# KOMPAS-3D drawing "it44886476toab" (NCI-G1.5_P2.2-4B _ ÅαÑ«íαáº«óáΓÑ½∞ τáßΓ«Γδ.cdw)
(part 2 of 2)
  Кривая без истории:10763
  Кривая без истории:10764
  Кривая без истории:10765
  Кривая без истории:10766
  Кривая без истории:10767
  Кривая без истории:10768
  Кривая без истории:10769
  Кривая без истории:10770
  Кривая без истории:10771
  Кривая без истории:10772
  Кривая без истории:10773
  Кривая без истории:10774
  Кривая без истории:10775
  Кривая без истории:10776
  Кривая без истории:10777
  Кривая без истории:10778
  Кривая без истории:10779
  Кривая без истории:10780
  Кривая без истории:10781
  Кривая без истории:10782
  Кривая без истории:10783
  Кривая без истории:10784
  Кривая без истории:10785
  Кривая без истории:10786
  Кривая без истории:10787
  Кривая без истории:10788
  Кривая без истории:10789
  Кривая без истории:10790
  Кривая без истории:10791
  Кривая без истории:10792
  Кривая без истории:10793
  Кривая без истории:10794
  Кривая без истории:10795
  Кривая без истории:10796
  Кривая без истории:10797
  Кривая без истории:10798
  Кривая без истории:10799
  Кривая без истории:10800
  Кривая без истории:10801
  Кривая без истории:10802
  Кривая без истории:10803
  Кривая без истории:10804
  Кривая без истории:10805
  Кривая без истории:10806
  Кривая без истории:10807
  Кривая без истории:10808
  Кривая без истории:10809
  Кривая без истории:10810
  Кривая без истории:10811
  Кривая без истории:10812
  Кривая без истории:10813
  Кривая без истории:10814
  Кривая без истории:10815
  Кривая без истории:10816
  Кривая без истории:10817
  Кривая без истории:10818
  Кривая без истории:10819
  Кривая без истории:10820
  Кривая без истории:10821
  Кривая без истории:10822
  Кривая без истории:10823
  Кривая без истории:10824
  Кривая без истории:10825
  Кривая без истории:10826
  Кривая без истории:10827
  Кривая без истории:10828
  Кривая без истории:10829
  Кривая без истории:10830
  Кривая без истории:10831
  Кривая без истории:10832
  Кривая без истории:10833
  Кривая без истории:10834
  Кривая без истории:10835
  Кривая без истории:10836
  Кривая без истории:10837
  Кривая без истории:10838
  Кривая без истории:10839
  Кривая без истории:10840
  Кривая без истории:10841
  Кривая без истории:10842
  Кривая без истории:10843
  Кривая без истории:10844
  Кривая без истории:10845
  Кривая без истории:10846
  Кривая без истории:10847
  Кривая без истории:10848
  Кривая без истории:10849
  Кривая без истории:10850
  Кривая без истории:10851
  Кривая без истории:10852
  Кривая без истории:10853
  Кривая без истории:10854
  Кривая без истории:10855
  Кривая без истории:10856
  Кривая без истории:10857
  Кривая без истории:10858
  Кривая без истории:10859
  Кривая без истории:10860
  Кривая без истории:10861
  Кривая без истории:10862
  Кривая без истории:10863
  Кривая без истории:10864
  Кривая без истории:10865
  Кривая без истории:10866
  Кривая без истории:10867
  Кривая без истории:10868
  Кривая без истории:10869
  Кривая без истории:10870
  Кривая без истории:10871
  Кривая без истории:10872
  Кривая без истории:10873
  Кривая без истории:10874
  Кривая без истории:10875
  Кривая без истории:10876
  Кривая без истории:10877
  Кривая без истории:10878
  Кривая без истории:10879
  Кривая без истории:10880
  Кривая без истории:10881
  Кривая без истории:10882
  Кривая без истории:10883
  Кривая без истории:10884
  Кривая без истории:10885
  Кривая без истории:10886
  Кривая без истории:10887
  Кривая без истории:10888
  Кривая без истории:10889
  Кривая без истории:10890
  Кривая без истории:10891
  Кривая без истории:10892
  Кривая без истории:10893
  Кривая без истории:10894
  Кривая без истории:10895
  Кривая без истории:10896
  Кривая без истории:10897
  Кривая без истории:10898
  Кривая без истории:10899
  Кривая без истории:10900
  Кривая без истории:10901
  Кривая без истории:10902
  Кривая без истории:10903
  Кривая без истории:10904
  Кривая без истории:10905
  Кривая без истории:10906
  Кривая без истории:10907
  Кривая без истории:10908
  Кривая без истории:10909
  Кривая без истории:10910
  Кривая без истории:10911
  Кривая без истории:10912
  Кривая без истории:10913
  Кривая без истории:10914
  Кривая без истории:10915
  Кривая без истории:10916
  Кривая без истории:10917
  Кривая без истории:10918
  Кривая без истории:10919
  Кривая без истории:10920
  Кривая без истории:10921
  Кривая без истории:10922
  Кривая без истории:10923
  Кривая без истории:10924
  Кривая без истории:10925
  Кривая без истории:10926
  Кривая без истории:10927
  Кривая без истории:10928
  Кривая без истории:10929
  Кривая без истории:10930
  Кривая без истории:10931
  Кривая без истории:10932
  Кривая без истории:10933
  Кривая без истории:10934
  Кривая без истории:10935
  Кривая без истории:10936
  Кривая без истории:10937
  Кривая без истории:10938
  Кривая без истории:10939
  Кривая без истории:10940
  Кривая без истории:10941
  Кривая без истории:10942
  Кривая без истории:10943
  Кривая без истории:10944
  Кривая без истории:10945
  Кривая без истории:10946
  Кривая без истории:10947
  Кривая без истории:10948
  Кривая без истории:10949
  Кривая без истории:10950
  Кривая без истории:10951
  Кривая без истории:10952
  Кривая без истории:10953
  Кривая без истории:10954
  Кривая без истории:10955
  Кривая без истории:10956
  Кривая без истории:10957
  Кривая без истории:10958
  Кривая без истории:10959
  Кривая без истории:10960
  Кривая без истории:10961
  Кривая без истории:10962
  Кривая без истории:10963
  Кривая без истории:10964
  Кривая без истории:10965
  Кривая без истории:10966
  Кривая без истории:10967
  Кривая без истории:10968
  Кривая без истории:10969
  Кривая без истории:10970
  Кривая без истории:10971
  Кривая без истории:10972
  Кривая без истории:10973
  Кривая без истории:10974
  Кривая без истории:10975
  Кривая без истории:10976
  Кривая без истории:10977
  Кривая без истории:10978
  Кривая без истории:10979
  Кривая без истории:10980
  Кривая без истории:10981
  Кривая без истории:10982
  Кривая без истории:10983
  Кривая без истории:10984
  Кривая без истории:10985
  Кривая без истории:10986
  Кривая без истории:10987
  Кривая без истории:10988
  Кривая без истории:10989
  Кривая без истории:10990
  Кривая без истории:10991
  Кривая без истории:10992
  Кривая без истории:10993
  Кривая без истории:10994
  Кривая без истории:10995
  Кривая без истории:10996
  Кривая без истории:10997
  Кривая без истории:10998
  Кривая без истории:10999
  Кривая без истории:11000
  Кривая без истории:11001
  Кривая без истории:11002
  Кривая без истории:11003
  Кривая без истории:11004
  Кривая без истории:11005
  Кривая без истории:11006
  Кривая без истории:11007
  Кривая без истории:11008
  Кривая без истории:11009
  Кривая без истории:11010
  Кривая без истории:11011
  Кривая без истории:11012
  Кривая без истории:11013
  Кривая без истории:11014
  Кривая без истории:11015
  Кривая без истории:11016
  Кривая без истории:11017
  Кривая без истории:11018
  Кривая без истории:11019
  Кривая без истории:11020
  Кривая без истории:11021
  Кривая без истории:11022
  Кривая без истории:11023
  Кривая без истории:11024
  Кривая без истории:11025
  Кривая без истории:11026
  Кривая без истории:11027
  Кривая без истории:11028
  Кривая без истории:11029
  Кривая без истории:11030
  Кривая без истории:11031
  Кривая без истории:11032
  Кривая без истории:11033
  Кривая без истории:11034
  Кривая без истории:11035
  Кривая без истории:11036
  Кривая без истории:11037
  Кривая без истории:11038
  Кривая без истории:11039
  Кривая без истории:11040
  Кривая без истории:11041
  Кривая без истории:11042
  Кривая без истории:11043
  Кривая без истории:11044
  Кривая без истории:11045
  Кривая без истории:11046
  Кривая без истории:11047
  Кривая без истории:11048
  Кривая без истории:11049
  Кривая без истории:11050
  Кривая без истории:11051
  Кривая без истории:11052
  Кривая без истории:11053
  Кривая без истории:11054
  Кривая без истории:11055
  Кривая без истории:11056
  Кривая без истории:11057
  Кривая без истории:11058
  Кривая без истории:11059
  Кривая без истории:11060
  Кривая без истории:11061
  Кривая без истории:11062
  Кривая без истории:11063
  Кривая без истории:11064
  Кривая без истории:11065
  Кривая без истории:11066
  Кривая без истории:11067
  Кривая без истории:11068
  Кривая без истории:11069
  Кривая без истории:11070
  Кривая без истории:11071
  Кривая без истории:11072
  Кривая без истории:11073
  Кривая без истории:11074
  Кривая без истории:11075
  Кривая без истории:11076
  Кривая без истории:11077
  Кривая без истории:11078
  Кривая без истории:11079
  Кривая без истории:11080
  Кривая без истории:11081
  Кривая без истории:11082
  Кривая без истории:11083
  Кривая без истории:11084
  Кривая без истории:11085
  Кривая без истории:11086
  Кривая без истории:11087
  Кривая без истории:11088
  Кривая без истории:11089
  Кривая без истории:11090
  Кривая без истории:11091
  Кривая без истории:11092
  Кривая без истории:11093
  Кривая без истории:11094
  Кривая без истории:11095
  Кривая без истории:11096
  Кривая без истории:11097
  Кривая без истории:11098
  Кривая без истории:11099
  Кривая без истории:11100
  Кривая без истории:11101
  Кривая без истории:11102
  Кривая без истории:11103
  Кривая без истории:11104
  Кривая без истории:11105
  Кривая без истории:11106
  Кривая без истории:11107
  Кривая без истории:11108
  Кривая без истории:11109
  Кривая без истории:11110
  Кривая без истории:11111
  Кривая без истории:11112
  Кривая без истории:11113
  Кривая без истории:11114
  Кривая без истории:11115
  Кривая без истории:11116
  Кривая без истории:11117
  Кривая без истории:11118
  Кривая без истории:11119
  Кривая без истории:11120
  Кривая без истории:11121
  Кривая без истории:11122
  Кривая без истории:11123
  Кривая без истории:11124
  Кривая без истории:11125
  Кривая без истории:11126
  Кривая без истории:11127
  Кривая без истории:11128
  Кривая без истории:11129
  Кривая без истории:11130
  Кривая без истории:11131
  Кривая без истории:11132
  Кривая без истории:11133
  Кривая без истории:11134
  Кривая без истории:11135
  Кривая без истории:11136
  Кривая без истории:11137
  Кривая без истории:11138
  Кривая без истории:11139
  Кривая без истории:11140
  Кривая без истории:11141
  Кривая без истории:11142
  Кривая без истории:11143
  Кривая без истории:11144
  Кривая без истории:11145
  Кривая без истории:11146
  Кривая без истории:11147
  Кривая без истории:11148
  Кривая без истории:11149
  Кривая без истории:11150
  Кривая без истории:11151
  Кривая без истории:11152
  Кривая без истории:11153
  Кривая без истории:11154
  Кривая без истории:11155
  Кривая без истории:11156
  Кривая без истории:11157
  Кривая без истории:11158
  Кривая без истории:11159
  Кривая без истории:11160
  Кривая без истории:11161
  Кривая без истории:11162
  Кривая без истории:11163
  Кривая без истории:11164
  Кривая без истории:11165
  Кривая без истории:11166
  Кривая без истории:11167
  Кривая без истории:11168
  Кривая без истории:11169
  Кривая без истории:11170
  Кривая без истории:11171
  Кривая без истории:11172
  Кривая без истории:11173
  Кривая без истории:11174
  Кривая без истории:11175
  Кривая без истории:11176
  Кривая без истории:11177
  Кривая без истории:11178
  Кривая без истории:11179
  Кривая без истории:11180
  Кривая без истории:11181
  Кривая без истории:11182
  Кривая без истории:11183
  Кривая без истории:11184
  Кривая без истории:11185
  Кривая без истории:11186
  Кривая без истории:11187
  Кривая без истории:11188
  Кривая без истории:11189
  Кривая без истории:11190
  Кривая без истории:11191
  Кривая без истории:11192
  Кривая без истории:11193
  Кривая без истории:11194
  Кривая без истории:11195
  Кривая без истории:11196
  Кривая без истории:11197
  Кривая без истории:11198
  Кривая без истории:11199
  Кривая без истории:11200
  Кривая без истории:11201
  Кривая без истории:11202
  Кривая без истории:11203
  Кривая без истории:11204
  Кривая без истории:11205
  Кривая без истории:11206
  Кривая без истории:11207
  Кривая без истории:11208
  Кривая без истории:11209
  Кривая без истории:11210
  Кривая без истории:11211
  Кривая без истории:11212
  Кривая без истории:11213
  Кривая без истории:11214
  Кривая без истории:11215
  Кривая без истории:11216
  Кривая без истории:11217
  Кривая без истории:11218
  Кривая без истории:11219
  Кривая без истории:11220
  Кривая без истории:11221
  Кривая без истории:11222
  Кривая без истории:11223
  Кривая без истории:11224
  Кривая без истории:11225
  Кривая без истории:11226
  Кривая без истории:11227
  Кривая без истории:11228
  Кривая без истории:11229
  Кривая без истории:11230
  Кривая без истории:11231
  Кривая без истории:11232
  Кривая без истории:11233
  Кривая без истории:11234
  Кривая без истории:11235
  Кривая без истории:11236
  Кривая без истории:11237
  Кривая без истории:11238
  Кривая без истории:11239
  Кривая без истории:11240
  Кривая без истории:11241
  Кривая без истории:11242
  Кривая без истории:11243
  Кривая без истории:11244
  Кривая без истории:11245
  Кривая без истории:11246
  Кривая без истории:11247
  Кривая без истории:11248
  Кривая без истории:11249
  Кривая без истории:11250
  Кривая без истории:11251
  Кривая без истории:11252
  Кривая без истории:11253
  Кривая без истории:11254
  Кривая без истории:11255
  Кривая без истории:11256
  Кривая без истории:11257
  Кривая без истории:11258
  Кривая без истории:11259
  Кривая без истории:11260
  Кривая без истории:11261
  Кривая без истории:11262
  Кривая без истории:11263
  Кривая без истории:11264
  Кривая без истории:11265
  Кривая без истории:11266
  Кривая без истории:11267
  Кривая без истории:11268
  Кривая без истории:11269
  Кривая без истории:11270
  Кривая без истории:11271
  Кривая без истории:11272
  Кривая без истории:11273
  Кривая без истории:11274
  Кривая без истории:11275
  Кривая без истории:11276
  Кривая без истории:11277
  Кривая без истории:11278
  Кривая без истории:11279
  Кривая без истории:11280
  Кривая без истории:11281
  Кривая без истории:11282
  Кривая без истории:11283
  Кривая без истории:11284
  Кривая без истории:11285
  Кривая без истории:11286
  Кривая без истории:11287
  Кривая без истории:11288
  Кривая без истории:11289
  Кривая без истории:11290
  Кривая без истории:11291
  Кривая без истории:11292
  Кривая без истории:11293
  Кривая без истории:11294
  Кривая без истории:11295
  Кривая без истории:11296
  Кривая без истории:11297
  Кривая без истории:11298
  Кривая без истории:11299
  Кривая без истории:11300
  Кривая без истории:11301
  Кривая без истории:11302
  Кривая без истории:11303
  Кривая без истории:11304
  Кривая без истории:11305
  Кривая без истории:11306
  Кривая без истории:11307
  Кривая без истории:11308
  Кривая без истории:11309
  Кривая без истории:11310
  Кривая без истории:11311
  Кривая без истории:11312
  Кривая без истории:11313
  Кривая без истории:11314
  Кривая без истории:11315
  Кривая без истории:11316
  Кривая без истории:11317
  Кривая без истории:11318
  Кривая без истории:11319
  Кривая без истории:11320
  Кривая без истории:11321
  Кривая без истории:11322
  Кривая без истории:11323
  Кривая без истории:11324
  Кривая без истории:11325
  Кривая без истории:11326
  Кривая без истории:11327
  Кривая без истории:11328
  Кривая без истории:11329
  Кривая без истории:11330
  Кривая без истории:11331
  Кривая без истории:11332
  Кривая без истории:11333
  Кривая без истории:11334
  Кривая без истории:11335
  Кривая без истории:11336
  Кривая без истории:11337
  Кривая без истории:11338
  Кривая без истории:11339
  Кривая без истории:11340
  Кривая без истории:11341
  Кривая без истории:11342
  Кривая без истории:11343
  Кривая без истории:11344
  Кривая без истории:11345
  Кривая без истории:11346
  Кривая без истории:11347
  Кривая без истории:11348
  Кривая без истории:11349
  Кривая без истории:11350
  Кривая без истории:11351
  Кривая без истории:11352
  Кривая без истории:11353
  Кривая без истории:11354
  Кривая без истории:11355
  Кривая без истории:11356
  Кривая без истории:11357
  Кривая без истории:11358
  Кривая без истории:11359
  Кривая без истории:11360
  Кривая без истории:11361
  Кривая без истории:11362
  Кривая без истории:11363
  Кривая без истории:11364
  Кривая без истории:11365
  Кривая без истории:11366
  Кривая без истории:11367
  Кривая без истории:11368
  Кривая без истории:11369
  Кривая без истории:11370
  Кривая без истории:11371
  Кривая без истории:11372
  Кривая без истории:11373
  Кривая без истории:11374
  Кривая без истории:11375
  Кривая без истории:11376
  Кривая без истории:11377
  Кривая без истории:11378
  Кривая без истории:11379
  Кривая без истории:11380
  Кривая без истории:11381
  Кривая без истории:11382
  Кривая без истории:11383
  Кривая без истории:11384
  Кривая без истории:11385
  Кривая без истории:11386
  Кривая без истории:11387
  Кривая без истории:11388
  Кривая без истории:11389
  Кривая без истории:11390
  Кривая без истории:11391
  Кривая без истории:11392
  Кривая без истории:11393
  Кривая без истории:11394
  Кривая без истории:11395
  Кривая без истории:11396
  Кривая без истории:11397
  Кривая без истории:11398
  Кривая без истории:11399
  Кривая без истории:11400
  Кривая без истории:11401
  Кривая без истории:11402
  Кривая без истории:11403
  Кривая без истории:11404
  Кривая без истории:11405
  Кривая без истории:11406
  Кривая без истории:11407
  Кривая без истории:11408
  Кривая без истории:11409
  Кривая без истории:11410
  Кривая без истории:11411
  Кривая без истории:11412
  Кривая без истории:11413
  Кривая без истории:11414
  Кривая без истории:11415
  Кривая без истории:11416
  Кривая без истории:11417
  Кривая без истории:11418
  Кривая без истории:11419
  Кривая без истории:11420
  Кривая без истории:11421
  Кривая без истории:11422
  Кривая без истории:11423
  Кривая без истории:11424
  Кривая без истории:11425
  Кривая без истории:11426
  Кривая без истории:11427
  Кривая без истории:11428
  Кривая без истории:11429
  Кривая без истории:11430
  Кривая без истории:11431
  Кривая без истории:11432
  Кривая без истории:11433
  Кривая без истории:11434
  Кривая без истории:11435
  Кривая без истории:11436
  Кривая без истории:11437
  Кривая без истории:11438
  Кривая без истории:11439
  Кривая без истории:11440
  Кривая без истории:11441
  Кривая без истории:11442
  Кривая без истории:11443
  Кривая без истории:11444
  Кривая без истории:11445
  Кривая без истории:11446
  Кривая без истории:11447
  Кривая без истории:11448
  Кривая без истории:11449
  Кривая без истории:11450
  Кривая без истории:11451
  Кривая без истории:11452
  Кривая без истории:11453
  Кривая без истории:11454
  Кривая без истории:11455
  Кривая без истории:11456
  Кривая без истории:11457
  Кривая без истории:11458
  Кривая без истории:11459
  Кривая без истории:11460
  Кривая без истории:11461
  Кривая без истории:11462
  Кривая без истории:11463
  Кривая без истории:11464
  Кривая без истории:11465
  Кривая без истории:11466
  Кривая без истории:11467
  Кривая без истории:11468
  Кривая без истории:11469
  Кривая без истории:11470
  Кривая без истории:11471
  Кривая без истории:11472
  Кривая без истории:11473
  Кривая без истории:11474
  Кривая без истории:11475
  Кривая без истории:11476
  Кривая без истории:11477
  Кривая без истории:11478
  Кривая без истории:11479
  Кривая без истории:11480
  Кривая без истории:11481
  Кривая без истории:11482
  Кривая без истории:11483
  Кривая без истории:11484
  Кривая без истории:11485
  Кривая без истории:11486
  Кривая без истории:11487
  Кривая без истории:11488
  Кривая без истории:11489
  Кривая без истории:11490
  Кривая без истории:11491
  Кривая без истории:11492
  Кривая без истории:11493
  Кривая без истории:11494
  Кривая без истории:11495
  Кривая без истории:11496
  Кривая без истории:11497
  Кривая без истории:11498
  Кривая без истории:11499
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Dimensions and other numbers on the sheet: 4±1; 1:1; 1; 13.01.25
